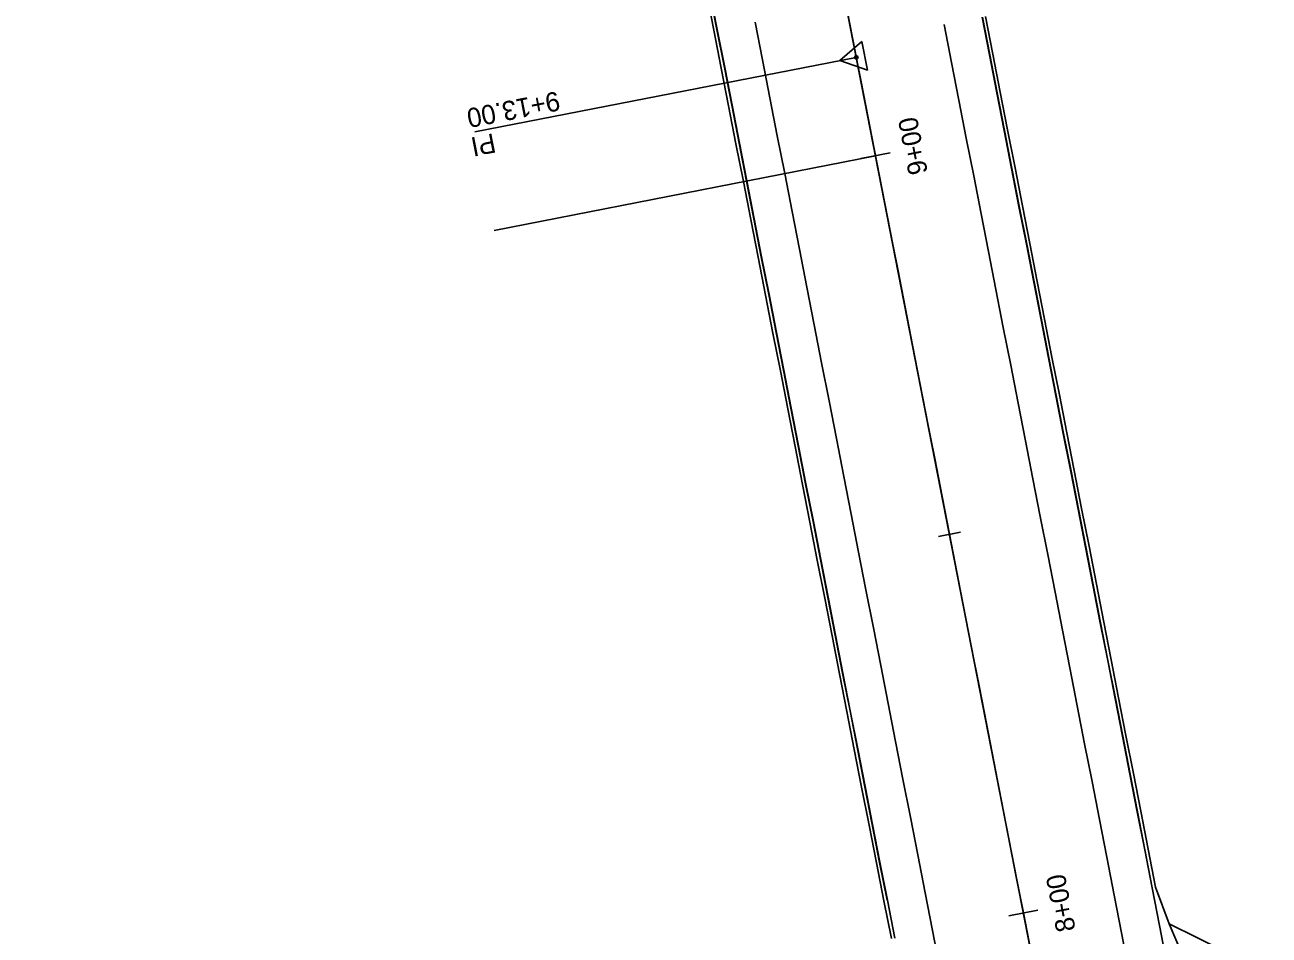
# Model space of a CAD drawing. Extents: x 1150550 to 1151113, y 1141187 to 1143500.
# Drawn here: x 1150711.8 to 1150873.1, y 1141786 to 1141904 of the extents above; entities that cross this region are included whole.
import ezdxf

# ---------------------------------------------------------------- set-up
doc = ezdxf.new("R2010")
doc.units = 0
for name, color, linetype in [('AC_P', 7, 'Continuous'), ('ACSC_P_T', 7, 'Continuous'), ('ACSCT_P', 7, 'Continuous'), ('ACSR_P_T', 7, 'Continuous'), ('ACSRT_P', 7, 'Continuous'), ('ADEFAULT', 7, 'Continuous'), ('Default', 7, 'Continuous'), ('LELB_P', 7, 'Continuous'), ('PE_P', 7, 'Continuous'), ('PET_P', 7, 'Continuous'), ('RC_P', 7, 'Continuous'), ('XSCTOP1_P', 7, 'Continuous')]:
    doc.layers.add(name, color=color, linetype=linetype)

msp = doc.modelspace()

# ---------------------------------------------------------------- linework, layer by layer
at = {"layer": 'AC_P'}
for p, q in [((1150819.56, 1141899.84), (1150776.47, 1142120.43)), ((1150956.27, 1141200.06), (1150819.56, 1141899.84))]:
    msp.add_line(p, q, dxfattribs=at)
msp.add_lwpolyline([(1150842.19, 1141784.03), (1150841.23, 1141788.93), (1150840.27, 1141793.84), (1150839.31, 1141798.75), (1150838.35, 1141803.65), (1150837.4, 1141808.56), (1150836.44, 1141813.47), (1150835.48, 1141818.38), (1150834.52, 1141823.28), (1150833.56, 1141828.19), (1150832.6, 1141833.1), (1150831.64, 1141838.01), (1150830.68, 1141842.91), (1150829.73, 1141847.82), (1150828.77, 1141852.73), (1150827.81, 1141857.63), (1150826.85, 1141862.54), (1150825.89, 1141867.45), (1150824.93, 1141872.36), (1150823.97, 1141877.26), (1150823.02, 1141882.17), (1150822.06, 1141887.08), (1150821.1, 1141891.99), (1150820.14, 1141896.89), (1150819.18, 1141901.8), (1150818.22, 1141906.71)], dxfattribs=at)
at = {"layer": 'ACSCT_P'}
msp.add_lwpolyline([(1150819.56, 1141899.84), (1150770.1, 1141890.17)], dxfattribs=at)
at = {"layer": 'ACSRT_P'}
for points in [[(1150820.17, 1141886.71), (1150823.94, 1141887.45)], [(1150830.23, 1141837.73), (1150833.06, 1141838.28)], [(1150839.35, 1141788.57), (1150843.11, 1141789.3)]]:
    msp.add_lwpolyline(points, dxfattribs=at)
at = {"layer": 'ADEFAULT'}
for points in [[(1150817.43, 1141899.42), (1150820.28, 1141901.9)], [(1150820.28, 1141901.9), (1150821, 1141898.19)], [(1150821, 1141898.19), (1150817.43, 1141899.42)]]:
    msp.add_lwpolyline(points, dxfattribs=at)
msp.add_circle((1150819.56, 1141899.84), 0.227, dxfattribs=at)
at = {"layer": 'Default'}
for p, q in [((1150956.27, 1141200.06), (1150657.48, 1142729.55)), ((1150822.06, 1141887.08), (1150772.59, 1141877.41))]:
    msp.add_line(p, q, dxfattribs=at)
for points in [[(1150823.59, 1141790.58), (1150822.63, 1141795.49), (1150821.67, 1141800.4), (1150820.71, 1141805.3), (1150819.75, 1141810.21), (1150818.79, 1141815.12), (1150817.83, 1141820.02), (1150816.88, 1141824.93), (1150815.92, 1141829.84), (1150814.96, 1141834.75), (1150814, 1141839.65), (1150813.04, 1141844.56), (1150812.08, 1141849.47), (1150811.12, 1141854.38), (1150810.17, 1141859.28), (1150809.21, 1141864.19), (1150808.25, 1141869.1), (1150807.29, 1141874), (1150806.33, 1141878.91), (1150805.37, 1141883.82), (1150804.41, 1141888.73), (1150803.45, 1141893.63), (1150802.5, 1141898.54), (1150801.54, 1141903.45), (1150800.58, 1141908.35)], [(1150823.59, 1141790.58), (1150822.63, 1141795.49), (1150821.67, 1141800.4), (1150820.71, 1141805.3), (1150819.75, 1141810.21), (1150818.79, 1141815.12), (1150817.83, 1141820.02), (1150816.88, 1141824.93), (1150815.92, 1141829.84), (1150814.96, 1141834.75), (1150814, 1141839.65), (1150813.04, 1141844.56), (1150812.08, 1141849.47), (1150811.12, 1141854.38), (1150810.17, 1141859.28), (1150809.21, 1141864.19), (1150808.25, 1141869.1), (1150807.29, 1141874), (1150806.33, 1141878.91), (1150805.37, 1141883.82), (1150804.41, 1141888.73), (1150803.45, 1141893.63), (1150802.5, 1141898.54), (1150801.54, 1141903.45), (1150800.58, 1141908.35)], [(1150856.96, 1141797.1), (1150856, 1141802.01), (1150855.04, 1141806.91), (1150854.08, 1141811.82), (1150853.12, 1141816.73), (1150852.16, 1141821.64), (1150851.2, 1141826.54), (1150850.25, 1141831.45), (1150849.29, 1141836.36), (1150848.33, 1141841.27), (1150847.37, 1141846.17), (1150846.41, 1141851.08), (1150845.45, 1141855.99), (1150844.49, 1141860.89), (1150843.53, 1141865.8), (1150842.58, 1141870.71), (1150841.62, 1141875.62), (1150840.66, 1141880.52), (1150839.7, 1141885.43), (1150838.74, 1141890.34), (1150837.78, 1141895.24), (1150836.82, 1141900.15), (1150835.87, 1141905.06)], [(1150856.96, 1141797.1), (1150856, 1141802.01), (1150855.04, 1141806.91), (1150854.08, 1141811.82), (1150853.12, 1141816.73), (1150852.16, 1141821.64), (1150851.2, 1141826.54), (1150850.25, 1141831.45), (1150849.29, 1141836.36), (1150848.33, 1141841.27), (1150847.37, 1141846.17), (1150846.41, 1141851.08), (1150845.45, 1141855.99), (1150844.49, 1141860.89), (1150843.53, 1141865.8), (1150842.58, 1141870.71), (1150841.62, 1141875.62), (1150840.66, 1141880.52), (1150839.7, 1141885.43), (1150838.74, 1141890.34), (1150837.78, 1141895.24), (1150836.82, 1141900.15), (1150835.87, 1141905.06)]]:
    msp.add_lwpolyline(points, dxfattribs=at)
at = {"layer": 'LELB_P'}
for points in [[(1150824.11, 1141785.59), (1150823.14, 1141790.49), (1150822.18, 1141795.4), (1150821.22, 1141800.31), (1150820.26, 1141805.21), (1150819.3, 1141810.12), (1150818.34, 1141815.03), (1150817.38, 1141819.94), (1150816.43, 1141824.84), (1150815.47, 1141829.75), (1150814.51, 1141834.66), (1150813.55, 1141839.57), (1150812.59, 1141844.47), (1150811.63, 1141849.38), (1150810.67, 1141854.29), (1150809.72, 1141859.19), (1150808.76, 1141864.1), (1150807.8, 1141869.01), (1150806.84, 1141873.92), (1150805.88, 1141878.82), (1150804.92, 1141883.73), (1150803.96, 1141888.64), (1150803, 1141893.55), (1150802.05, 1141898.45), (1150801.09, 1141903.36), (1150800.13, 1141908.27)], [(1150823.55, 1141790.57), (1150822.59, 1141795.48), (1150821.63, 1141800.39), (1150820.67, 1141805.29), (1150819.71, 1141810.2), (1150818.75, 1141815.11), (1150817.79, 1141820.02), (1150816.83, 1141824.92), (1150815.88, 1141829.83), (1150814.92, 1141834.74), (1150813.96, 1141839.65), (1150813, 1141844.55), (1150812.04, 1141849.46), (1150811.08, 1141854.37), (1150810.12, 1141859.27), (1150809.17, 1141864.18), (1150808.21, 1141869.09), (1150807.25, 1141874), (1150806.29, 1141878.9), (1150805.33, 1141883.81), (1150804.37, 1141888.72), (1150803.41, 1141893.63), (1150802.46, 1141898.53), (1150801.5, 1141903.44), (1150800.54, 1141908.35)], [(1150857, 1141797.11), (1150856.04, 1141802.02), (1150855.08, 1141806.92), (1150854.12, 1141811.83), (1150853.16, 1141816.74), (1150852.2, 1141821.64), (1150851.24, 1141826.55), (1150850.29, 1141831.46), (1150849.33, 1141836.37), (1150848.37, 1141841.27), (1150847.41, 1141846.18), (1150846.45, 1141851.09), (1150845.49, 1141855.99), (1150844.53, 1141860.9), (1150843.58, 1141865.81), (1150842.62, 1141870.72), (1150841.66, 1141875.62), (1150840.7, 1141880.53), (1150839.74, 1141885.44), (1150838.78, 1141890.35), (1150837.82, 1141895.25), (1150836.86, 1141900.16), (1150835.91, 1141905.07)], [(1150836.31, 1141905.15), (1150837.27, 1141900.24), (1150838.23, 1141895.33), (1150839.19, 1141890.43), (1150840.15, 1141885.52), (1150841.11, 1141880.61), (1150842.07, 1141875.7), (1150843.03, 1141870.8), (1150843.98, 1141865.89), (1150844.94, 1141860.98), (1150845.9, 1141856.07), (1150846.86, 1141851.17), (1150847.82, 1141846.26), (1150848.78, 1141841.35), (1150849.74, 1141836.45), (1150850.69, 1141831.54), (1150851.65, 1141826.63), (1150852.61, 1141821.72), (1150853.57, 1141816.82), (1150854.53, 1141811.91), (1150855.49, 1141807), (1150856.45, 1141802.1), (1150857.41, 1141797.19), (1150858.34, 1141792.28), (1150860.13, 1141787.53), (1150867.47, 1141783.87)], [(1150862.12, 1141782.83), (1150860.13, 1141787.53), (1150858.34, 1141792.28)]]:
    msp.add_lwpolyline(points, dxfattribs=at)
at = {"layer": 'PE_P'}
for points in [[(1150824.55, 1141785.67), (1150823.59, 1141790.58), (1150822.63, 1141795.49), (1150821.67, 1141800.4), (1150820.71, 1141805.3), (1150819.75, 1141810.21), (1150818.79, 1141815.12), (1150817.83, 1141820.02), (1150816.88, 1141824.93), (1150815.92, 1141829.84), (1150814.96, 1141834.75), (1150814, 1141839.65), (1150813.04, 1141844.56), (1150812.08, 1141849.47), (1150811.12, 1141854.38), (1150810.17, 1141859.28), (1150809.21, 1141864.19), (1150808.25, 1141869.1), (1150807.29, 1141874), (1150806.33, 1141878.91), (1150805.37, 1141883.82), (1150804.41, 1141888.73), (1150803.45, 1141893.63), (1150802.5, 1141898.54), (1150801.54, 1141903.45), (1150800.58, 1141908.35)], [(1150823.59, 1141790.58), (1150822.63, 1141795.49), (1150821.67, 1141800.4), (1150820.71, 1141805.3), (1150819.75, 1141810.21), (1150818.79, 1141815.12), (1150817.83, 1141820.02), (1150816.88, 1141824.93), (1150815.92, 1141829.84), (1150814.96, 1141834.75), (1150814, 1141839.65), (1150813.04, 1141844.56), (1150812.08, 1141849.47), (1150811.12, 1141854.38), (1150810.17, 1141859.28), (1150809.21, 1141864.19), (1150808.25, 1141869.1), (1150807.29, 1141874), (1150806.33, 1141878.91), (1150805.37, 1141883.82), (1150804.41, 1141888.73), (1150803.45, 1141893.63), (1150802.5, 1141898.54), (1150801.54, 1141903.45), (1150800.58, 1141908.35)], [(1150859.83, 1141782.38), (1150858.87, 1141787.29), (1150857.91, 1141792.19), (1150856.96, 1141797.1), (1150856, 1141802.01), (1150855.04, 1141806.91), (1150854.08, 1141811.82), (1150853.12, 1141816.73), (1150852.16, 1141821.64), (1150851.2, 1141826.54), (1150850.25, 1141831.45), (1150849.29, 1141836.36), (1150848.33, 1141841.27), (1150847.37, 1141846.17), (1150846.41, 1141851.08), (1150845.45, 1141855.99), (1150844.49, 1141860.89), (1150843.53, 1141865.8), (1150842.58, 1141870.71), (1150841.62, 1141875.62), (1150840.66, 1141880.52), (1150839.7, 1141885.43), (1150838.74, 1141890.34), (1150837.78, 1141895.24), (1150836.82, 1141900.15), (1150835.87, 1141905.06)]]:
    msp.add_lwpolyline(points, dxfattribs=at)
at = {"layer": 'PET_P'}
for points in [[(1150830.41, 1141781.73), (1150829.45, 1141786.63), (1150828.49, 1141791.54), (1150827.53, 1141796.45), (1150826.58, 1141801.35), (1150825.62, 1141806.26), (1150824.66, 1141811.17), (1150823.7, 1141816.08), (1150822.74, 1141820.98), (1150821.78, 1141825.89), (1150820.82, 1141830.8), (1150819.87, 1141835.7), (1150818.91, 1141840.61), (1150817.95, 1141845.52), (1150816.99, 1141850.43), (1150816.03, 1141855.33), (1150815.07, 1141860.24), (1150814.11, 1141865.15), (1150813.16, 1141870.06), (1150812.2, 1141874.96), (1150811.24, 1141879.87), (1150810.28, 1141884.78), (1150809.32, 1141889.68), (1150808.36, 1141894.59), (1150807.4, 1141899.5), (1150806.44, 1141904.41)], [(1150854.92, 1141781.42), (1150853.97, 1141786.33), (1150853.01, 1141791.23), (1150852.05, 1141796.14), (1150851.09, 1141801.05), (1150850.13, 1141805.96), (1150849.17, 1141810.86), (1150848.21, 1141815.77), (1150847.26, 1141820.68), (1150846.3, 1141825.58), (1150845.34, 1141830.49), (1150844.38, 1141835.4), (1150843.42, 1141840.31), (1150842.46, 1141845.21), (1150841.5, 1141850.12), (1150840.54, 1141855.03), (1150839.59, 1141859.94), (1150838.63, 1141864.84), (1150837.67, 1141869.75), (1150836.71, 1141874.66), (1150835.75, 1141879.56), (1150834.79, 1141884.47), (1150833.83, 1141889.38), (1150832.88, 1141894.29), (1150831.92, 1141899.19), (1150830.96, 1141904.1)]]:
    msp.add_lwpolyline(points, dxfattribs=at)
at = {"layer": 'RC_P'}
for points in [[(1150823.14, 1141790.49), (1150822.18, 1141795.4), (1150821.22, 1141800.31), (1150820.26, 1141805.21), (1150819.3, 1141810.12), (1150818.34, 1141815.03), (1150817.38, 1141819.94), (1150816.43, 1141824.84), (1150815.47, 1141829.75), (1150814.51, 1141834.66), (1150813.55, 1141839.57), (1150812.59, 1141844.47), (1150811.63, 1141849.38), (1150810.67, 1141854.29), (1150809.72, 1141859.19), (1150808.76, 1141864.1), (1150807.8, 1141869.01), (1150806.84, 1141873.92), (1150805.88, 1141878.82), (1150804.92, 1141883.73), (1150803.96, 1141888.64), (1150803, 1141893.55), (1150802.05, 1141898.45), (1150801.09, 1141903.36), (1150800.13, 1141908.27)], [(1150823.14, 1141790.49), (1150822.18, 1141795.4), (1150821.22, 1141800.31), (1150820.26, 1141805.21), (1150819.3, 1141810.12), (1150818.34, 1141815.03), (1150817.38, 1141819.94), (1150816.43, 1141824.84), (1150815.47, 1141829.75), (1150814.51, 1141834.66), (1150813.55, 1141839.57), (1150812.59, 1141844.47), (1150811.63, 1141849.38), (1150810.67, 1141854.29), (1150809.72, 1141859.19), (1150808.76, 1141864.1), (1150807.8, 1141869.01), (1150806.84, 1141873.92), (1150805.88, 1141878.82), (1150804.92, 1141883.73), (1150803.96, 1141888.64), (1150803, 1141893.55), (1150802.05, 1141898.45), (1150801.09, 1141903.36), (1150800.13, 1141908.27)], [(1150857.41, 1141797.19), (1150856.45, 1141802.1), (1150855.49, 1141807), (1150854.53, 1141811.91), (1150853.57, 1141816.82), (1150852.61, 1141821.72), (1150851.65, 1141826.63), (1150850.69, 1141831.54), (1150849.74, 1141836.45), (1150848.78, 1141841.35), (1150847.82, 1141846.26), (1150846.86, 1141851.17), (1150845.9, 1141856.07), (1150844.94, 1141860.98), (1150843.98, 1141865.89), (1150843.03, 1141870.8), (1150842.07, 1141875.7), (1150841.11, 1141880.61), (1150840.15, 1141885.52), (1150839.19, 1141890.43), (1150838.23, 1141895.33), (1150837.27, 1141900.24), (1150836.31, 1141905.15)], [(1150857.41, 1141797.19), (1150856.45, 1141802.1), (1150855.49, 1141807), (1150854.53, 1141811.91), (1150853.57, 1141816.82), (1150852.61, 1141821.72), (1150851.65, 1141826.63), (1150850.69, 1141831.54), (1150849.74, 1141836.45), (1150848.78, 1141841.35), (1150847.82, 1141846.26), (1150846.86, 1141851.17), (1150845.9, 1141856.07), (1150844.94, 1141860.98), (1150843.98, 1141865.89), (1150843.03, 1141870.8), (1150842.07, 1141875.7), (1150841.11, 1141880.61), (1150840.15, 1141885.52), (1150839.19, 1141890.43), (1150838.23, 1141895.33), (1150837.27, 1141900.24), (1150836.31, 1141905.15)]]:
    msp.add_lwpolyline(points, dxfattribs=at)
at = {"layer": 'XSCTOP1_P'}
for points in [[(1150824.55, 1141785.67), (1150823.59, 1141790.58), (1150822.63, 1141795.49), (1150821.67, 1141800.4), (1150820.71, 1141805.3), (1150819.75, 1141810.21), (1150818.79, 1141815.12), (1150817.83, 1141820.02), (1150816.88, 1141824.93), (1150815.92, 1141829.84), (1150814.96, 1141834.75), (1150814, 1141839.65), (1150813.04, 1141844.56), (1150812.08, 1141849.47), (1150811.12, 1141854.38), (1150810.17, 1141859.28), (1150809.21, 1141864.19), (1150808.25, 1141869.1), (1150807.29, 1141874), (1150806.33, 1141878.91), (1150805.37, 1141883.82), (1150804.41, 1141888.73), (1150803.45, 1141893.63), (1150802.5, 1141898.54), (1150801.54, 1141903.45), (1150800.58, 1141908.35)], [(1150842.19, 1141784.03), (1150841.23, 1141788.93), (1150840.27, 1141793.84), (1150839.31, 1141798.75), (1150838.35, 1141803.65), (1150837.4, 1141808.56), (1150836.44, 1141813.47), (1150835.48, 1141818.38), (1150834.52, 1141823.28), (1150833.56, 1141828.19), (1150832.6, 1141833.1), (1150831.64, 1141838.01), (1150830.68, 1141842.91), (1150829.73, 1141847.82), (1150828.77, 1141852.73), (1150827.81, 1141857.63), (1150826.85, 1141862.54), (1150825.89, 1141867.45), (1150824.93, 1141872.36), (1150823.97, 1141877.26), (1150823.02, 1141882.17), (1150822.06, 1141887.08), (1150821.1, 1141891.99), (1150820.14, 1141896.89), (1150819.18, 1141901.8), (1150818.22, 1141906.71)], [(1150859.83, 1141782.38), (1150858.87, 1141787.29), (1150857.91, 1141792.19), (1150856.96, 1141797.1), (1150856, 1141802.01), (1150855.04, 1141806.91), (1150854.08, 1141811.82), (1150853.12, 1141816.73), (1150852.16, 1141821.64), (1150851.2, 1141826.54), (1150850.25, 1141831.45), (1150849.29, 1141836.36), (1150848.33, 1141841.27), (1150847.37, 1141846.17), (1150846.41, 1141851.08), (1150845.45, 1141855.99), (1150844.49, 1141860.89), (1150843.53, 1141865.8), (1150842.58, 1141870.71), (1150841.62, 1141875.62), (1150840.66, 1141880.52), (1150839.7, 1141885.43), (1150838.74, 1141890.34), (1150837.78, 1141895.24), (1150836.82, 1141900.15), (1150835.87, 1141905.06)], [(1150830.41, 1141781.73), (1150829.45, 1141786.63), (1150828.49, 1141791.54), (1150827.53, 1141796.45), (1150826.58, 1141801.35), (1150825.62, 1141806.26), (1150824.66, 1141811.17), (1150823.7, 1141816.08), (1150822.74, 1141820.98), (1150821.78, 1141825.89), (1150820.82, 1141830.8), (1150819.87, 1141835.7), (1150818.91, 1141840.61), (1150817.95, 1141845.52), (1150816.99, 1141850.43), (1150816.03, 1141855.33), (1150815.07, 1141860.24), (1150814.11, 1141865.15), (1150813.16, 1141870.06), (1150812.2, 1141874.96), (1150811.24, 1141879.87), (1150810.28, 1141884.78), (1150809.32, 1141889.68), (1150808.36, 1141894.59), (1150807.4, 1141899.5), (1150806.44, 1141904.41)], [(1150854.92, 1141781.42), (1150853.97, 1141786.33), (1150853.01, 1141791.23), (1150852.05, 1141796.14), (1150851.09, 1141801.05), (1150850.13, 1141805.96), (1150849.17, 1141810.86), (1150848.21, 1141815.77), (1150847.26, 1141820.68), (1150846.3, 1141825.58), (1150845.34, 1141830.49), (1150844.38, 1141835.4), (1150843.42, 1141840.31), (1150842.46, 1141845.21), (1150841.5, 1141850.12), (1150840.54, 1141855.03), (1150839.59, 1141859.94), (1150838.63, 1141864.84), (1150837.67, 1141869.75), (1150836.71, 1141874.66), (1150835.75, 1141879.56), (1150834.79, 1141884.47), (1150833.83, 1141889.38), (1150832.88, 1141894.29), (1150831.92, 1141899.19), (1150830.96, 1141904.1)]]:
    msp.add_lwpolyline(points, dxfattribs=at)

# ---------------------------------------------------------------- texts
at = {"layer": 'ACSC_P_T'}
for s, p in [('9+13.00', (1150780.85, 1141895.46)), ('PI', (1150772.52, 1141890.01))]:
    msp.add_text(s, height=2.501, rotation=191.0539, dxfattribs=at).set_placement(p)
at = {"layer": 'ACSR_P_T'}
for s, p in [('9+00', (1150828.85, 1141884.88)), ('8+00', (1150848.02, 1141786.73))]:
    msp.add_text(s, height=2.501, rotation=101.0539, dxfattribs=at).set_placement(p)

doc.saveas('drawing.dxf')
